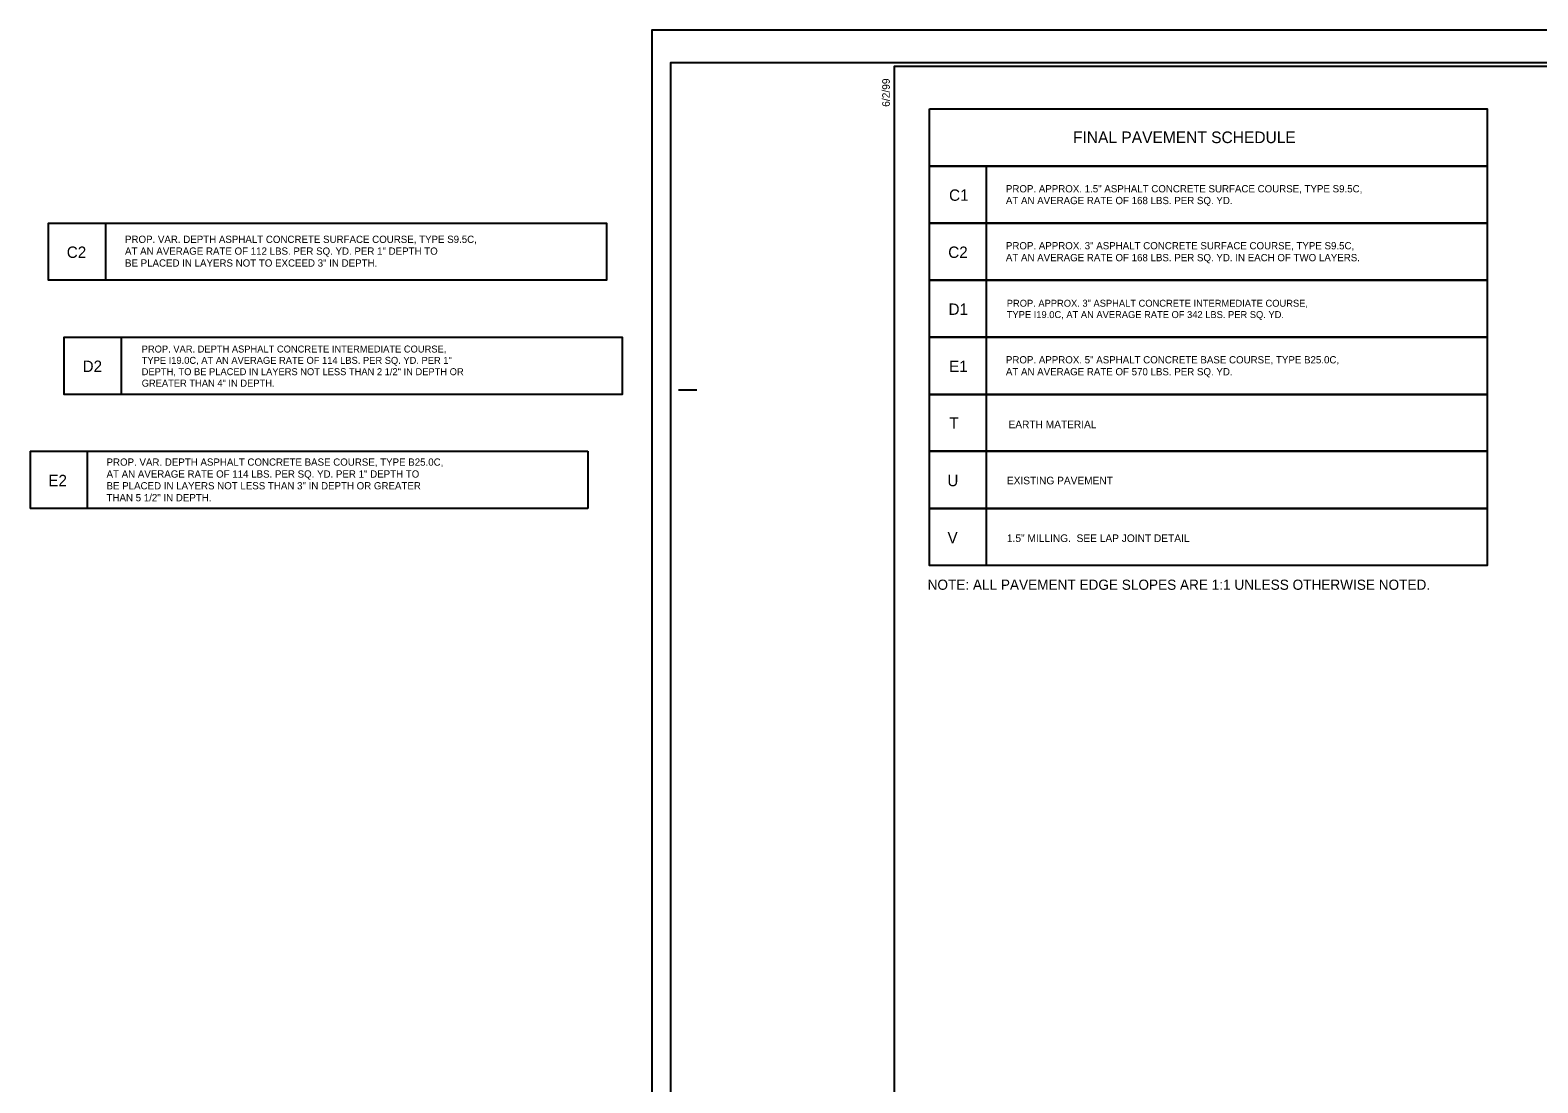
# Model space of a CAD drawing. Extents: x 2111095 to 2115970, y 670428 to 672393.
# Drawn here: x 2111156 to 2112193, y 671492 to 672216 of the extents above; entities that cross this region are included whole.
import ezdxf

# ---------------------------------------------------------------- set-up
doc = ezdxf.new("R2010")
doc.units = 0
for name, color, linetype in [('Old_Level_1', 7, 'Continuous'), ('Old_Level_19', 7, 'Continuous'), ('Old_Level_21', 7, 'Continuous'), ('Prop Pavement Schedule Description CELL', 7, 'Continuous'), ('Sheet Cutting Line CELL', 7, 'Continuous'), ('Sheet Plot Border Inside CELL', 7, 'Continuous'), ('Sheet Plot Border Outside CELL', 7, 'Continuous'), ('Sheet Typical CELL', 7, 'Continuous')]:
    doc.layers.add(name, color=color, linetype=linetype)

msp = doc.modelspace()

# ---------------------------------------------------------------- linework, layer by layer
at = {"layer": 'Old_Level_19'}
for p, q in [((2111563.1, 672004.7), (2111563.1, 671965.4)), ((2111155.6, 671926.2), (2111539.6, 671926.2)), ((2111155.6, 671926.2), (2111155.6, 671886.9)), ((2111194.9, 671926.2), (2111194.9, 671886.9)), ((2111539.6, 671926.2), (2111539.6, 671886.9)), ((2111814, 671926.2), (2111774.7, 671926.2)), ((2111539.6, 671886.9), (2111155.6, 671886.9))]:
    msp.add_line(p, q, dxfattribs=at)
msp.add_lwpolyline([(2111774.7, 672161.8), (2112158.7, 672161.8), (2112158.7, 672122.5), (2111774.7, 672122.5)], close=True, dxfattribs=at)
for points in [[(2111814, 672083.2), (2111774.7, 672083.2), (2111774.7, 672122.5), (2112158.7, 672122.5), (2112158.7, 672083.2), (2111814, 672083.2), (2111814, 672122.5)], [(2111207.6, 672044), (2111168.3, 672044), (2111168.3, 672083.2), (2111552.3, 672083.2), (2111552.3, 672044), (2111207.6, 672044), (2111207.6, 672083.2)], [(2111814, 672044), (2111774.7, 672044), (2111774.7, 672083.2), (2112158.7, 672083.2), (2112158.7, 672044), (2111814, 672044), (2111814, 672083.2)], [(2111814, 671965.4), (2111774.7, 671965.4), (2111774.7, 672004.7), (2112158.7, 672004.7), (2112158.7, 671965.4), (2111814, 671965.4), (2111814, 672004.7)], [(2111814, 671926.2), (2111774.7, 671926.2), (2111774.7, 671965.4), (2112158.7, 671965.4), (2112158.7, 671926.2), (2111814, 671926.2), (2111814, 671965.4)], [(2111814, 671886.9), (2111774.7, 671886.9), (2111774.7, 671926.2), (2112158.7, 671926.2), (2112158.7, 671886.9), (2111814, 671886.9), (2111814, 671926.2)], [(2111814, 671847.6), (2111774.7, 671847.6), (2111774.7, 671886.9), (2112158.7, 671886.9), (2112158.7, 671847.6), (2111814, 671847.6), (2111814, 671886.9)]]:
    msp.add_lwpolyline(points, dxfattribs=at)
at = {"layer": 'Prop Pavement Schedule Description CELL'}
for points in [[(2111814, 672004.7), (2111774.7, 672004.7), (2111774.7, 672044), (2112158.7, 672044), (2112158.7, 672004.7), (2111814, 672004.7), (2111814, 672044)], [(2111218.4, 671965.4), (2111179.1, 671965.4), (2111179.1, 672004.7), (2111563.1, 672004.7), (2111563.1, 671965.4), (2111218.4, 671965.4), (2111218.4, 672004.7)]]:
    msp.add_lwpolyline(points, dxfattribs=at)
at = {"layer": 'Sheet Cutting Line CELL'}
for p, q in [((2113267.5, 672216), (2111583.5, 672216)), ((2111583.5, 672216), (2111583.5, 671116))]:
    msp.add_line(p, q, dxfattribs=at)
at = {"layer": 'Sheet Plot Border Inside CELL'}
msp.add_lwpolyline([(2113263, 672193.6), (2111596.5, 672193.6), (2111596.5, 671138.5), (2113263, 671138.5)], close=True, dxfattribs=at)
at = {"layer": 'Sheet Plot Border Outside CELL'}
msp.add_lwpolyline([(2113267.5, 672216), (2111583.5, 672216), (2111583.5, 671116), (2113267.5, 671116)], close=True, dxfattribs=at)
at = {"layer": 'Sheet Typical CELL'}
msp.add_line((2111602, 671968.5), (2111614.5, 671968.5), dxfattribs=at)
msp.add_lwpolyline([(2113250.5, 672191), (2111750.5, 672191), (2111750.5, 671141), (2113250.5, 671141)], close=True, dxfattribs=at)

# ---------------------------------------------------------------- texts
at = {"layer": 'Old_Level_1'}
msp.add_text('NOTE: ALL PAVEMENT EDGE SLOPES ARE 1:1 UNLESS OTHERWISE NOTED.', height=7, dxfattribs=at).set_placement((2111773.4, 671830.9))
at = {"layer": 'Old_Level_21'}
for s, height, p in [('FINAL PAVEMENT SCHEDULE', 8, (2111873.5, 672138.3)), ('C1', 7.84, (2111788.2, 672098.6)), ('C2', 7.84, (2111180.8, 672059.3)), ('C2', 7.84, (2111787.6, 672059.3)), ('E1', 7.84, (2111788.2, 671980.8)), ('T ', 7.84, (2111788.3, 671941.8)), ('EARTH MATERIAL', 5.224, (2111829.1, 671942.1)), ('E2', 7.84, (2111168.1, 671902.2)), ('U ', 7.84, (2111787, 671902.2)), ('EXISTING PAVEMENT', 5.224, (2111828, 671903.5)), ('V ', 7.85, (2111787.1, 671862.9)), ('1.5" MILLING.  SEE LAP JOINT DETAIL', 5.231, (2111828, 671863.8))]:
    msp.add_text(s, height=height, dxfattribs=at).set_placement(p)
at = {"layer": 'Prop Pavement Schedule Description CELL'}
for s, height, p in [('AT AN AVERAGE RATE OF 168 LBS. PER SQ. YD.', 5, (2111827.3, 672096.3)), ('PROP. APPROX. 1.5" ASPHALT CONCRETE SURFACE COURSE, TYPE S9.5C,', 5, (2111827.3, 672104.4)), ('PROP. VAR. DEPTH ASPHALT CONCRETE SURFACE COURSE, TYPE S9.5C,', 5, (2111220.9, 672069.6)), ('PROP. APPROX. 3" ASPHALT CONCRETE SURFACE COURSE, TYPE S9.5C,', 5, (2111827.3, 672065.2)), ('AT AN AVERAGE RATE OF 112 LBS. PER SQ. YD. PER 1" DEPTH TO', 5, (2111220.9, 672061.5)), ('AT AN AVERAGE RATE OF 168 LBS. PER SQ. YD. IN EACH OF TWO LAYERS.', 5, (2111827.3, 672057)), ('BE PLACED IN LAYERS NOT TO EXCEED 3" IN DEPTH.', 5, (2111220.9, 672053.3)), ('PROP. APPROX. 3" ASPHALT CONCRETE INTERMEDIATE COURSE,', 4.8, (2111827.9, 672025.7)), ('D1', 7.84, (2111787.8, 672020.1)), ('TYPE I19.0C, AT AN AVERAGE RATE OF 342 LBS. PER SQ. YD.', 4.8, (2111827.9, 672017.9)), ('PROP. VAR. DEPTH ASPHALT CONCRETE INTERMEDIATE COURSE,', 4.8, (2111232.4, 671994.2)), ('D2', 7.84, (2111191.7, 671980.8)), ('TYPE I19.0C, AT AN AVERAGE RATE OF 114 LBS. PER SQ. YD. PER 1" ', 4.8, (2111232.4, 671986.4)), ('PROP. APPROX. 5" ASPHALT CONCRETE BASE COURSE, TYPE B25.0C,', 5, (2111827.3, 671986.7)), ('DEPTH, TO BE PLACED IN LAYERS NOT LESS THAN 2 1/2" IN DEPTH OR', 4.8, (2111232.4, 671978.6)), ('AT AN AVERAGE RATE OF 570 LBS. PER SQ. YD.', 5, (2111827.3, 671978.5)), ('GREATER THAN 4" IN DEPTH.', 4.8, (2111232.4, 671970.7)), ('PROP. VAR. DEPTH ASPHALT CONCRETE BASE COURSE, TYPE B25.0C,', 5, (2111208.2, 671916.3)), ('AT AN AVERAGE RATE OF 114 LBS. PER SQ. YD. PER 1" DEPTH TO', 5, (2111208.2, 671908.1)), ('BE PLACED IN LAYERS NOT LESS THAN 3" IN DEPTH OR GREATER', 5, (2111208.2, 671900)), ('THAN 5 1/2" IN DEPTH.', 5, (2111208.2, 671891.8))]:
    msp.add_text(s, height=height, dxfattribs=at).set_placement(p)
at = {"layer": 'Sheet Typical CELL'}
msp.add_text('6/2/99', height=5.25, rotation=90, dxfattribs=at).set_placement((2111747.4, 672163.3))

doc.saveas('drawing.dxf')
